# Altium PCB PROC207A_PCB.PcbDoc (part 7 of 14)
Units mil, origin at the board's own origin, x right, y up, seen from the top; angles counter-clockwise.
Board outline 4094.49 x 3724.79 mil, 8 copper layers (Top Layer, L2_GND1, L3_SIG1, L4_PWR1, L5_PWR2, L6_SIG2, L7_GND2, Bottom Layer), stack 58.1 mil thick; 584 components, 399 nets, 8440 pads, 5258 vias.
Unrouted connection lines stored in the file: 9.
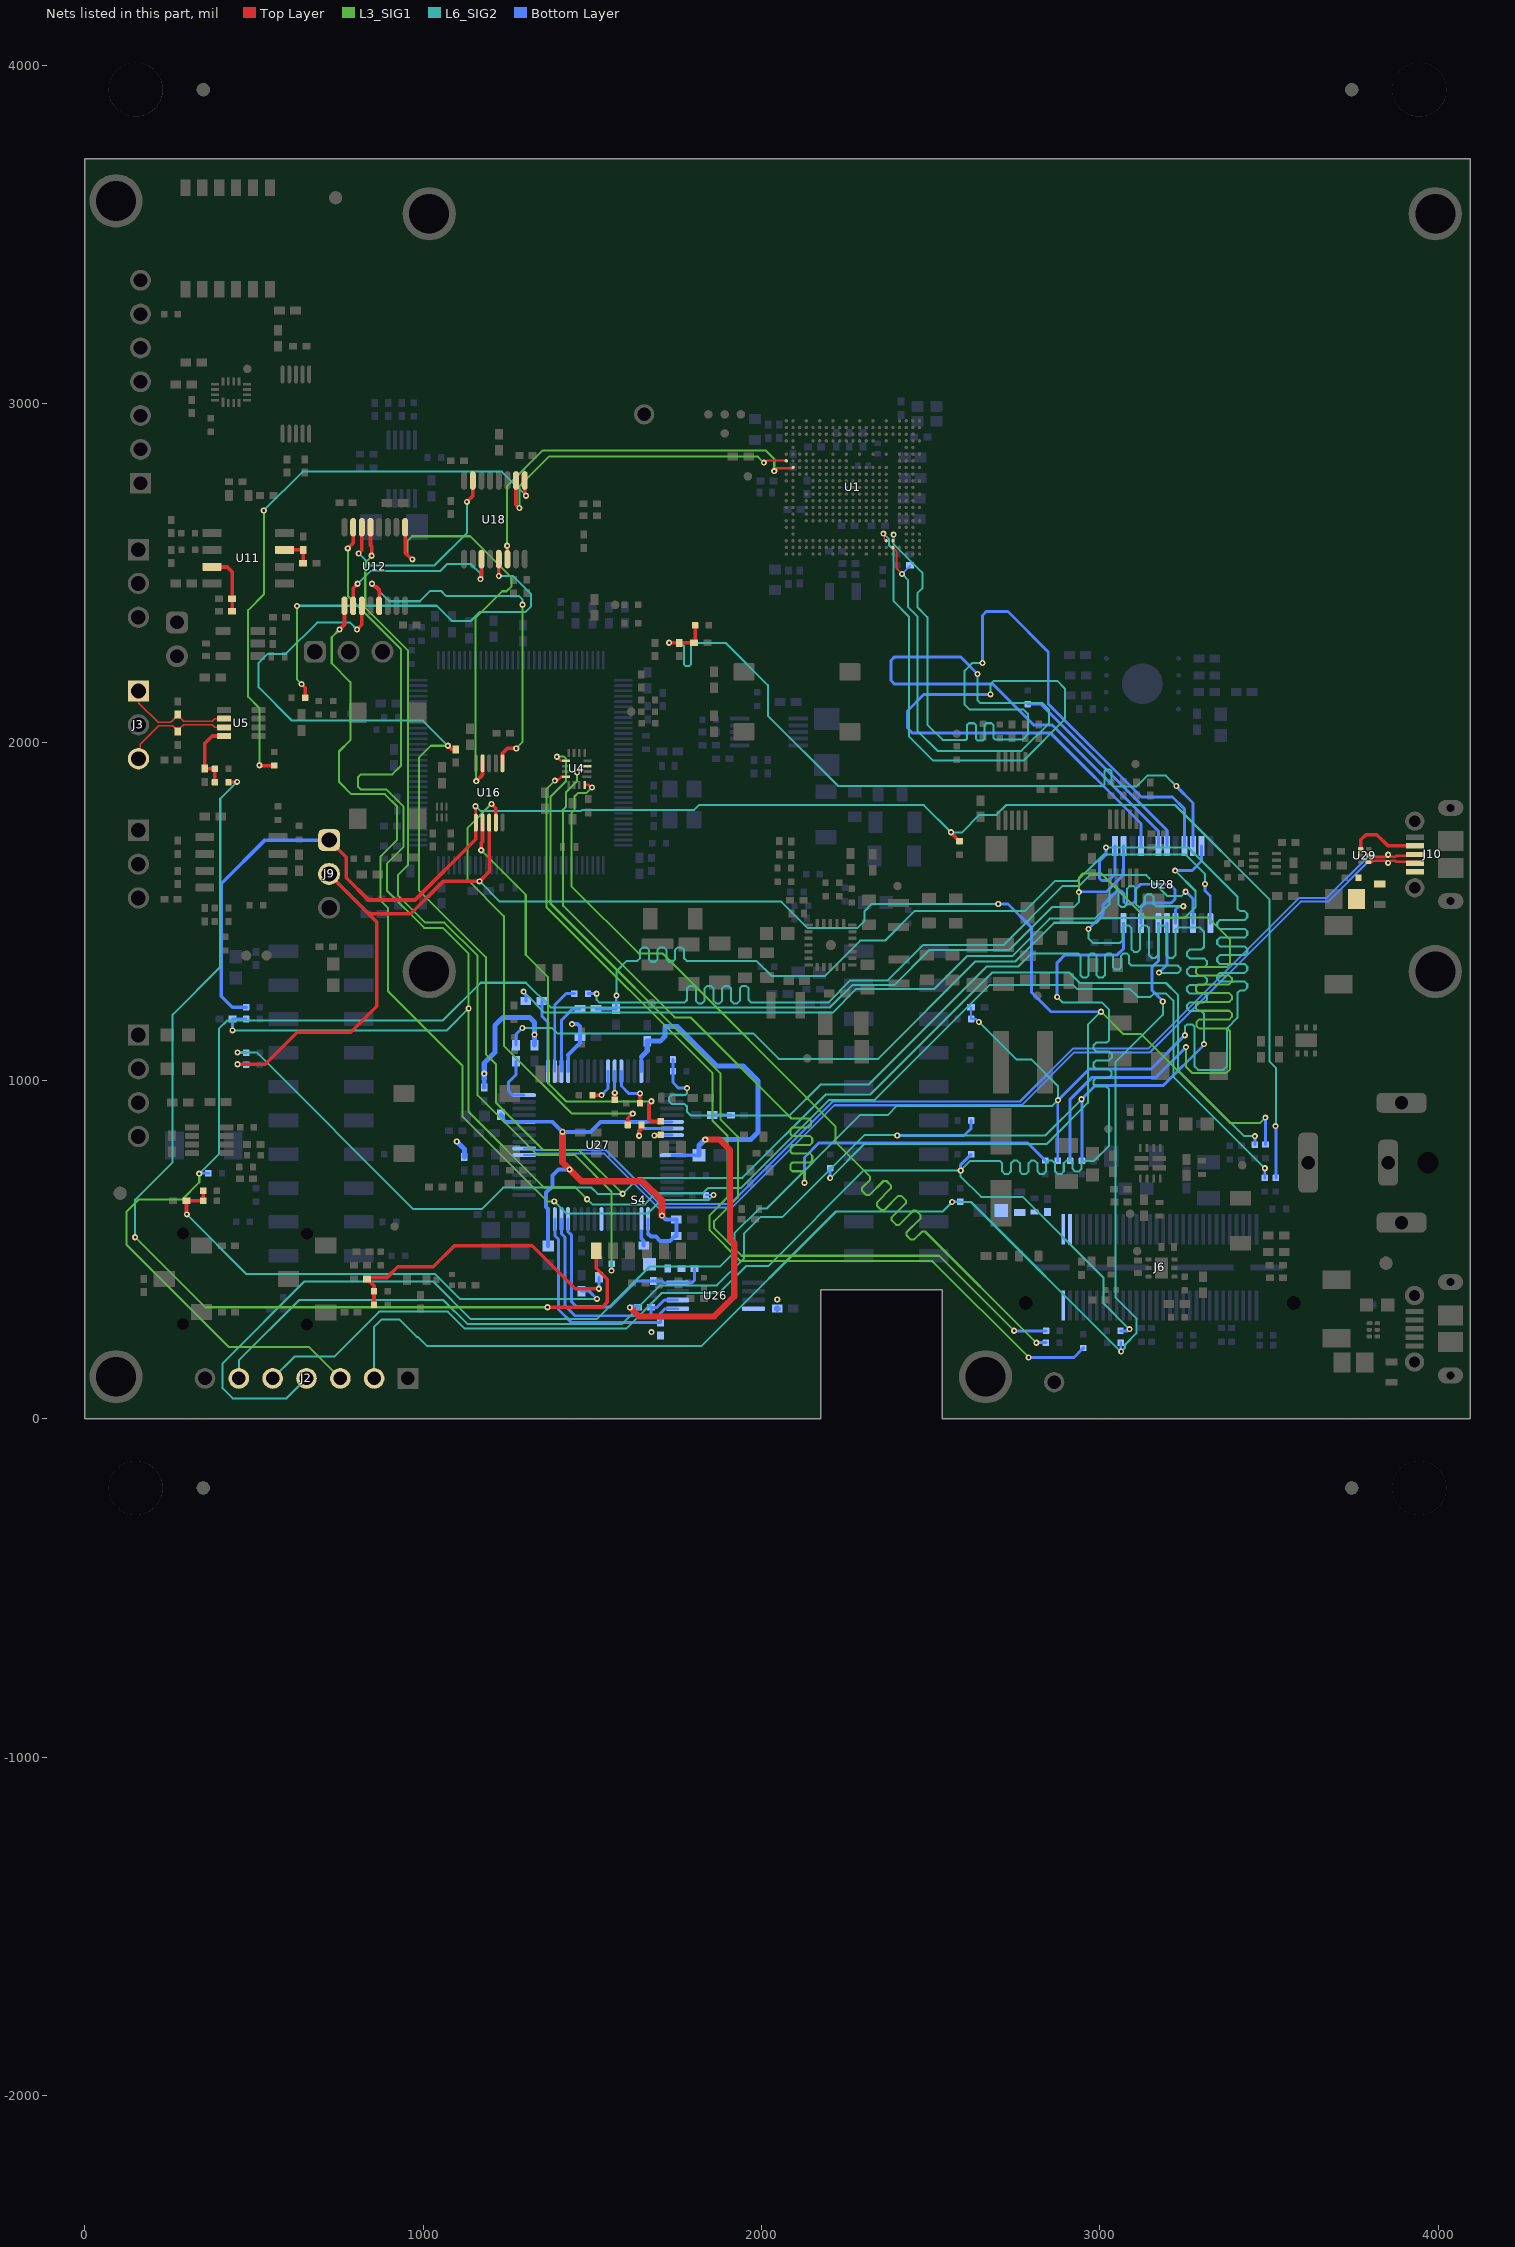
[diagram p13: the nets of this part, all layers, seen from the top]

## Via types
v1: diameter 13.77, hole 7, Top Layer to L2_GND1, tented top, 4306 vias
v2: diameter 18, hole 8, Top Layer to Bottom Layer, tented both sides, 946 vias
v3: diameter 19.68, hole 8, Top Layer to Bottom Layer, tented both sides, 6 vias

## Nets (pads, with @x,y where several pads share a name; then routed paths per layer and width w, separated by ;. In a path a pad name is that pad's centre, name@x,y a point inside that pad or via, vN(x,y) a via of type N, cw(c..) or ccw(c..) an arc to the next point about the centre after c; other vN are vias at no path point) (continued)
CAN_FD_H: J3.3 R68.2 U5.7 | length 335.9
  Top Layer w4.3: J3.3@158.23,1951.41 163.25,1956.42 163.25,1994.38 218.41,2049.54 258.93,2049.54 266.49,2041.98 266.49,2041.51 273.71,2034.29 274.18,2034.29 R68.2@274.18,2031.85 ; R68.2@274.18,2034.64 275,2034.64 281.87,2041.51 281.87,2042.33 291.5,2051.95 376.56,2051.95 384.46,2044.06 U5.7@411.27,2044.06
CAN_FD_L: J3.1 R79.1 U5.6 | length 332.4
  Top Layer w4.3: J3.1@158.23,2151.41 159.7,2149.95 159.7,2115.98 216.34,2059.34 253.84,2059.34 266.49,2071.99 266.49,2072.19 R79.1@274.18,2079.88 ; R79.1@274.18,2081.85 R79.1@274.18,2079.88 ; U5.6@411.27,2069.65 384.46,2069.65 376.56,2061.75 292.32,2061.75 281.88,2072.19 R79.1@274.18,2079.88
CAN_FD_RX: R80.1 U18.5 | length 1212
  Top Layer w10.8: v2(640.3,2171.85) 651.32,2160.83 R80.1@651.32,2132.1 ; U18.5@1223.27,2541.56 1223.38,2541.44 1223.38,2491.76 v2(1223.5,2491.65)
  L3_SIG1 w6: v2(627.14,2402.65) 627.14,2185.02 v2(640.3,2171.85)
  L6_SIG2 w6: v2(627.14,2402.65) 628.06,2403.58 1039.61,2403.58 1084.25,2358.93 1141.19,2358.93 1167.77,2385.51 1302.58,2385.51 1318.08,2401.02 1318.08,2438.63 1265.06,2491.65 v2(1223.5,2491.65)
CAN_FD_TX: R78.1 U18.9 | length 1730.1
  Top Layer w10.8: v2(515.55,1931.96) 516.43,1931.08 R78.1@559.82,1931.08 ; U18.9@1300.04,2773.84 1300.04,2734.71 1304.03,2730.71 v2(1304.03,2728.77)
  L3_SIG1 w6: v2(515.55,1931.96) 515.55,2101.32 482.32,2134.55 482.32,2390.56 528.65,2436.9 v2(528.65,2685.28)
  L6_SIG2 w6: v2(528.65,2685.28) 643.45,2800.07 1232.73,2800.07 v2(1304.03,2728.77)
CAN_FD_UARTA_RX: U1.Y8 U18.6 | length 1155.5
  Top Layer w8: v2(2037.65,2801.29) 2046.44,2810.09 2090.45,2810.09 2092.66,2812.3 U1.Y8@2093.15,2812.3
  Top Layer w10.8: v2(1248.01,2581) 1248.43,2580.57 1248.43,2541.98 U18.6@1248.86,2541.56
  L3_SIG1 w6: v2(1248.01,2581) 1248.01,2757.64 1352.17,2861.81 2013.17,2861.81 2025,2849.98 2037.65,2837.33 v2(2037.65,2801.29)
CAN_FD_UARTA_TX: U1.AA7 U18.10 | length 985.5
  Top Layer w6: v2(2006.99,2826.66) 2010.24,2826.66 2016.23,2832.65 2072.81,2832.65 U1.AA7@2073.47,2831.99
  Top Layer w10.8: U18.10@1274.45,2773.84 1274.45,2701.85 v2@1283.85,2692.44
  L3_SIG1 w6: v2(1284.02,2692.61) 1284.02,2757.06 1371.46,2844.49 1989.16,2844.49 v2(2006.99,2826.66)
CAN_STB: R3.2 R71.2 R273.2 U5.8 | length 210.6
  Top Layer w10.8: R3.2@384.18,1881.85 R273.2@384.18,1921.85 R71.2@354.18,1921.85 354.18,1996.18 376.47,2018.47 U5.8@411.27,2018.47
CAN_STB_CTRL: R3.1 S4.1 | length 3150.3
  Top Layer w10.8: R3.1@424.54,1881.85 448.85,1881.85 v2(450,1883) ; v2(1367.57,329.83) 1528.82,329.83 1544.1,345.11 1544.1,412.9 1511.51,445.49 S4.1@1511.51,496.87
  L3_SIG1 w6: v2(148.34,536.68) 355.19,329.83 v2(1367.57,329.83)
  L6_SIG2 w6: v2(148.34,536.68) 148.34,647.84 259.37,758.88 259.37,1195.03 400,1335.65 400,1833 v2(450,1883)
CONN_5V: C92.1 C93.1 C96.2 J6.1 J6.2 J6.3 R30.2
DCA_LP_FTDI_HOST_INTR_1: R81.2 R261.2 R276.1 U28.10 | length 2289.3
  Top Layer w10.8: v2(1726.91,2294.09) R261.2@1757.13,2294.09 1757.38,2294.33 R276.1@1800.3,2294.33 1803.93,2297.96 R81.2@1803.93,2345.54
  L6_SIG2 w6: v2(1726.91,2294.09) 1762.33,2294.09 1770.52,2285.89 1770.52,2230.07 1775.62,2224.97 1785.82,2224.97 1790.92,2230.07 1790.92,2288.99 1796.02,2294.09 1893.54,2294.09 2019,2168.63 2019,2078 2226,1871 3010.63,1871 3014.49,1874.86 3014.49,1914.66 3019.59,1919.76 3029.79,1919.76 3034.89,1914.66 3034.89,1874.86 3039.99,1869.76 3108.73,1869.76 3140.49,1901.52 3195.22,1901.52 v2(3226.13,1870.61)
  Bottom Layer w8.7: v2(3226.13,1870.61) 3226.13,1870.1 3275.37,1820.87 U28.10@3275.37,1693.39
DCA_LP_FTDI_SPIA_CLK: U1.F19 U28.4 | length 2741
  Top Layer w4: v2(2360.3,2616.69) 2362.57,2614.43 2362.57,2601.94 U1.F19@2368.75,2595.77
  L6_SIG2 w6: v2(2360.3,2616.69) 2377.31,2599.68 2377.31,2581.54 2389.55,2569.3 2389.55,2418 2435.85,2371.69 2435.85,2018.2 2508.08,1945.97 2774.35,1945.97 2897.78,2069.4 2897.78,2157.5 2874.03,2181.25 2686.1,2181.25 2676.86,2172.01 v2(2676.86,2141.67)
  Bottom Layer w8.7: v2(2676.86,2141.67) 2480.34,2141.67 2431.19,2092.51 2431.19,2041.87 2446.22,2026.83 2855.21,2026.83 3121.82,1760.22 U28.4@3121.82,1693.39
DCA_LP_FTDI_SPIA_CS: R246.1 U1.E20 U28.6 | length 2757.4
  Top Layer w4: U1.E20@2388.43,2576.08 2399.35,2565.16 2399.35,2550.22
  Top Layer w6: 2399.12,2550.22 2399.12,2513.98 v2(2415.49,2497.61)
  L6_SIG2 w6: v2(2415.49,2497.61) 2433.72,2479.38 2433.72,2399.49 2460.77,2372.44 2460.77,2033.68 2520.13,1974.32 2768.34,1974.32 2850.43,2056.41 2850.43,2096.44 2831.01,2115.86 2646.6,2115.86 2638.61,2123.85 v2(2638.61,2202.01)
  Bottom Layer w4: v2(2415.49,2497.61) 2439.12,2521.24 R246.1@2439.12,2523.33
  Bottom Layer w8.7: v2(2638.61,2202.01) 2588,2252.62 2393.57,2252.62 2382.42,2241.47 2382.42,2182.27 2392.9,2171.79 2683.94,2171.79 2804.27,2051.45 2858.85,2051.45 3173,1737.3 U28.6@3173,1693.39
DCA_LP_FTDI_SPIA_MISO: R284.1 U28.7 | length 612.5
  Bottom Layer w8.7: R284.1@2787,2112.82 2825.59,2112.82 3198.59,1739.82 U28.7@3198.59,1693.39
DCA_LP_FTDI_SPIA_MOSI: U1.E19 U28.9 | length 2738
  Top Layer w4: U1.E19@2388.43,2595.77 2388.94,2596.27 2388.94,2611.99 v2(2390.69,2613.75)
  L6_SIG2 w6: v2(2390.69,2613.75) 2390.69,2585.9 2475.34,2501.25 2475.34,2455.09 2460.63,2440.38 2460.63,2399.86 2490.34,2370.15 2490.34,2051.94 2535.22,2007.06 2604.5,2007.06 2607.46,2010.03 2607.46,2050.99 2612.66,2056.19 2628.26,2056.19 2633.46,2050.99 2633.46,2010.03 2638.66,2004.83 2654.26,2004.83 2659.46,2010.03 2659.46,2050.99 2664.66,2056.19 2680.26,2056.19 2685.46,2050.99 2685.46,2013.01 2690.66,2007.81 2771.73,2007.81 2787.18,2023.26 2787.18,2084.46 2775.15,2096.49 2615.41,2096.49 2600.46,2111.43 2600.46,2211.94 2622.93,2234.4 v2(2653.01,2234.4)
  Bottom Layer w8.7: v2(2653.01,2234.4) 2653.01,2375.07 2664.2,2386.26 2728.35,2386.26 2847.67,2266.93 2847.67,2113.37 3123.16,1837.88 3215.13,1837.88 3249.77,1803.24 U28.9@3249.77,1693.39
DCA_LP_FTDI_UARTA_RX: U12.5 U16.6 | length 1090
  Top Layer w10.8: v2(848.58,2468.46) 857.66,2459.37 862.05,2459.37 869.69,2451.74 U12.5@869.69,2403.24 ; U16.6@1234.33,1937.85 1234.33,1967.62 1248.53,1981.82 v2(1274.86,1981.82)
  L3_SIG1 w6: v2(1274.86,1981.82) 1293.22,2000.18 v2(1293.22,2406.58)
  L6_SIG2 w6: v2(848.58,2468.46) 900.17,2416.87 989.72,2416.87 1020.36,2447.51 1052.49,2447.51 1067.01,2432.99 1282.65,2432.99 1293.22,2422.42 v2(1293.22,2406.58)
DCA_LP_FTDI_UARTA_TX: U12.9 U16.9 | length 1244.2
  Top Layer w10.8: U12.9@946.46,2635.52 946.46,2560.05 965.88,2540.63 v2(967.81,2540.63) ; v2(1156.63,1884.99) 1156.79,1884.99 1175.28,1903.47 U16.9@1175.28,1937.85
  L3_SIG1 w6: v2(967.81,2540.63) 954.15,2554.28 954.15,2595.9 967.26,2609 1138.74,2609 1261.53,2486.21 1261.53,2461.8 1246.18,2446.45 1233.64,2446.45 1154.18,2366.99 1154.18,1960.86 1156.63,1958.42 v2(1156.63,1884.99)
DCA_LP_HOST_INTR_1: J2.2 R42.2 R223.2 U28.19 | length 4198.8
  L6_SIG2 w6: J2.2@854.92,119.45 854.92,272.12 876.8,294 928.56,294 980.41,242.15 984,242.15 1010.65,215.5 1822.94,215.5 2220.24,612.8 2535.38,612.8 v2(2563.66,641.08) 2619.37,641.08 3061.52,198.93 v2(3063.04,198.93) 3075.08,210.97 3075.08,219.79 3108.12,252.83 3108.12,297.29 3046.05,359.37 3046.05,1054.09 3186.19,1194.23 v2(3186.19,1233.93)
  Bottom Layer w8.7: v2(2563.66,641.08) 2564.22,641.64 R223.2@2587.42,641.64 ; v2@3061.92,202.02 R42.2@3061.92,225.06 ; U28.19@3173,1465.05 3173,1353.12 3153.78,1333.9 3153.78,1267.82 3186.19,1235.41 v2(3186.19,1233.93)
DCA_LP_RS232_RX: R61.1 R163.1 R178.1 U12.3 | length 6741.8
  Top Layer w10.8: v2(804.3,2333.27) 818.51,2347.48 U12.3@818.51,2403.24 ; v2(1072.67,1989.7) 1083.03,1979.33 R163.1@1096.46,1979.33
  L3_SIG1 w6: v2(1072.67,1989.7) 1022.63,1989.7 987.23,1954.3 987.23,1562.77 1185,1365 1185,1078.11 1215.73,1047.38 1215.73,933.58 1354.56,794.75 1460.07,794.75 v2(1589.52,665.3)
  L6_SIG2 w6: v2(450.77,1083.11) 507.44,1083.11 970.7,619.86 1173.07,619.86 1236.5,683.29 1497.43,683.29 1515.42,665.3 v2(1589.52,665.3) 1636.46,712.23 1943.23,712.23 2189.85,958.85 2321.16,958.85 2681.8,1319.49 2910.02,1319.49 2941.06,1288.45 3195.67,1288.45 3230.97,1253.14 3230.97,1032.03 3427.27,835.73 v2(3458.23,835.73) ; v2(804.3,2333.27) 783.74,2353.83 686.61,2353.83 593.87,2261.09 539.9,2261.09 513.58,2234.77 513.58,2162.14 612.04,2063.68 998.68,2063.68 v2(1072.67,1989.7)
  Bottom Layer w8.7: v2(450.77,1083.11) 451.32,1082.56 476.13,1082.56 R178.1@476.69,1082 ; v2(3458.23,835.73) 3458.35,835.61 R61.1@3458.35,810.38
DCA_LP_RS232_TX: R62.1 R156.1 R176.1 U12.15 | length 6088
  Top Layer w10.8: v2(776.95,2573.24) 792.92,2589.21 U12.15@792.92,2635.52
  L3_SIG1 w6: v2(776.95,2573.24) 776.95,2432.3 934.91,2274.33 934.91,1931.27 908.67,1905.03 815.91,1905.03 806.65,1895.77 806.65,1869.25 814.97,1860.93 891.06,1860.93 941.55,1810.44 941.55,1690.04 892.74,1641.23 892.74,1561.86 1002.98,1451.63 1057.41,1451.63 1134.26,1374.77 v2(1134.26,1213.18) 1134.26,906.98 1356.81,684.43 1449.29,684.43 v2(1484.69,649.03)
  L6_SIG2 w6: v2(436.29,1148.35) 436.57,1148.07 1069.15,1148.07 v2(1134.26,1213.18) ; v2(1484.69,649.03) 1499.72,634 1655.11,634 1687.97,666.86 1826.35,666.86 1841.49,682 1938.67,682 2199.67,943 2335.08,943 2674.97,1282.9 2920.59,1282.9 2933.32,1270.16 3090.13,1270.16 3113.41,1246.88 3149.46,1246.88 3159.76,1257.17 3196.04,1257.17 3217.26,1235.96 3217.26,1011.15 v2(3487.76,740.65)
  Bottom Layer w8.7: v2(436.29,1148.35) 436.49,1148.55 436.49,1181.8 R156.1@436.69,1182 R176.1@476.69,1182 ; R62.1@3487.69,712.42 v2(3487.76,740.65) v2(3487.76,740.65)
DCA_LP_SPIA_CLK: J2.3 R41.1 R210.1 U28.2 | length 7185.7
  L3_SIG1 w6: v2(337.89,724.65) 337.89,698.83 287.45,648.4 158.52,648.4 123.12,613 123.12,513.88 424.36,212.64 661.73,212.64 J2.3@754.92,119.45 ; v2(2938.09,1556.86) 2938.09,1599.99 2950.1,1612 3004.71,1612 3135.08,1481.62 3320.9,1481.62 3384.44,1418.08 3384.44,1373.1 3384.44,1344.1 3376.64,1336.3 3291.88,1336.3 3284.08,1328.5 3284.08,1318.1 3291.88,1310.3 3382.41,1310.3 3390.21,1302.5 3390.21,1292.1 3382.41,1284.3 3291.88,1284.3 3284.08,1276.5 3284.08,1266.1 3291.88,1258.3 3382.41,1258.3 3390.21,1250.5 3390.21,1240.1 3382.41,1232.3 3291.88,1232.3 3284.08,1224.5 3284.08,1214.1 3291.88,1206.3 3382.41,1206.3 3390.21,1198.5 3390.21,1188.1 3382.41,1180.3 3293.12,1180.3 3285.32,1172.5 3285.32,1162.1 3293.12,1154.3 3376.64,1154.3 3384.44,1146.5 3384.44,1107.61 3384.44,1032.54 3374.22,1022.32 3272.83,1022.32 3254.89,1040.27 v2(3254.89,1098.65)
  L6_SIG2 w6: v2(337.89,724.65) 395.98,782.75 395.98,1152.6 421.3,1177.91 1058.45,1177.91 1169.61,1289.07 1303.52,1289.07 1376.39,1216.2 2202.56,1216.2 2268.64,1282.28 2392.36,1282.28 2495.92,1385.84 2732.08,1385.84 2858.74,1512.5 2923.3,1512.5 2938.09,1527.28 v2(2938.09,1556.86)
  Bottom Layer w8.7: v2(337.89,724.65) 339.24,726 R210.1@364.65,726 ; R41.1@2912.47,762.75 2912.47,944.88 2976.03,1008.44 3164.67,1008.44 v2(3254.89,1098.65) ; v2(2938.09,1556.86) 2939.37,1558.14 3019.84,1558.14 3070.64,1608.93 U28.2@3070.64,1693.39
DCA_LP_SPIA_CS: J2.4 R39.1 R173.1 R177.2 U28.1 | length 6484.4
  L6_SIG2 w6: J2.4@654.92,119.45 595.93,60.46 436.54,60.46 406.99,90.01 406.99,164.2 648.74,405.95 1029.51,405.95 1140.96,294.51 1513.35,294.51 1668.84,450 1876.64,450 1919.49,492.85 1919.49,548.06 1993.06,621.64 2014.83,621.64 2291.99,898.8 2374.29,898.8 2400.38,924.89 2859.49,924.89 v2(2876.51,941.92) 2876.51,983.72 2797.73,1062.5 2753.33,1062.5 v2(2642.48,1173.35) ; v2(3018.05,1688.88) 3262.04,1688.88 3406.91,1544.01 3406.91,1511.41 3406.91,1508.41 3414.71,1500.61 3428.12,1500.61 3435.92,1492.81 3435.92,1482.41 3428.12,1474.61 3354.99,1474.61 3347.19,1466.81 3347.19,1456.41 3354.99,1448.61 3428.12,1448.61 3435.92,1440.81 3435.92,1430.41 3428.12,1422.61 3354.99,1422.61 3347.19,1414.81 3347.19,1404.41 3354.99,1396.61 3428.12,1396.61 3435.92,1388.81 3435.92,1378.41 3428.12,1370.61 3354.99,1370.61 3347.19,1362.81 3347.19,1352.41 3354.99,1344.61 3428.12,1344.61 3435.92,1336.81 3435.92,1326.41 3428.12,1318.61 3354.99,1318.61 3347.19,1310.81 3347.19,1300.41 3354.99,1292.61 3428.12,1292.61 3435.92,1284.81 3435.92,1274.41 3428.12,1266.61 3414.71,1266.61 3406.91,1258.81 3406.91,1231.05 3406.91,1185.07 3376.37,1154.52 3376.37,1042.29 3365.46,1031.38 3290.98,1031.38 3279.93,1042.43 3279.93,1159.25 3272.95,1166.23 3258.14,1166.23 3251.92,1160 3251.92,1134.32 v2(3251.43,1133.83)
  Bottom Layer w6: R177.2@2619.84,1182 2633.83,1182 v2(2642.48,1173.35) ; R177.2@2619.84,1182 R173.1@2619.86,1216.29
  Bottom Layer w8.7: R39.1@2875.7,762.75 v2@2875.7,941.92 ; v2(2876.51,941.92) 2969.05,1034.45 3152.05,1034.45 v2(3251.43,1133.83) ; v2(3018.05,1688.88) 3018.05,1666.45 2999.29,1647.69 2999.29,1597.68 3005.91,1591.06 3026.28,1591.06 3045.05,1609.83 U28.1@3045.05,1693.39
DCA_LP_SPIA_MISO: J2.5 R53.2 R221.2 U28.23 | length 5137.9
  L6_SIG2 w6: J2.5@554.92,119.45 619.47,184 737,184 870,317 1072.86,317 1122.94,266.92 1600.32,266.92 1705.88,372.48 1875.23,372.48 1954.08,451.33 2019.35,451.33 2302.41,734.39 v2(2588.84,734.39) ; v2(2873.93,1246.88) 2889.76,1231.05 3005.63,1231.05 3027.5,1209.18 3027.5,1119.6 3019.7,1111.8 2989.17,1111.8 2981.37,1104 2981.37,1093.6 2989.17,1085.8 3027.69,1085.8 3035.49,1078 3035.49,1067.6 3027.69,1059.8 2989.17,1059.8 2981.37,1052 2981.37,1041.6 2989.17,1033.8 3026.25,1033.8 3034.05,1026 3034.05,1015.6 3026.25,1007.8 2989.17,1007.8 2981.37,1000 2981.37,989.6 2989.17,981.8 3019.7,981.8 3027.5,974 3027.5,807.1 2982.92,762.52 2953.26,762.52 2945.46,754.72 2945.46,738.61 2937.66,730.81 2927.26,730.81 2919.46,738.61 2919.46,755.68 2911.66,763.48 2901.26,763.48 2893.46,755.68 2893.46,731.41 2885.66,723.61 2875.26,723.61 2867.46,731.41 2867.46,755.68 2859.66,763.48 2849.26,763.48 2841.46,755.68 2841.46,731.41 2833.66,723.61 2823.26,723.61 2815.46,731.41 2815.46,755.68 2807.66,763.48 2797.26,763.48 2789.46,755.68 2789.46,731.41 2781.66,723.61 2771.26,723.61 2763.46,731.41 2763.46,755.68 2755.66,763.48 2745.26,763.48 2737.46,755.68 2737.46,731.41 2729.66,723.61 2719.26,723.61 2711.46,731.41 2711.46,754.72 2703.66,762.52 2616.97,762.52 v2(2588.84,734.39) ; v2(3087.5,265.08) 3010.91,341.68 3010.91,416.76 2771.68,655.99 2648.98,655.99 2588.84,716.13 v2(2588.84,734.39)
  Bottom Layer w8.7: v2@2588.84,735.37 2588.84,750.99 R221.2@2619.84,782 ; v2(2873.93,1246.88) 2873.93,1348.36 2897.16,1371.58 3051.63,1371.58 3070.64,1390.59 U28.23@3070.64,1465.05 ; R53.2@3061.32,260.03 3082.45,260.03 v2(3087.5,265.08)
DCA_LP_SPIA_MOSI: J2.6 R52.1 R201.2 U28.21 | length 6033.3
  L6_SIG2 w6: J2.6@454.92,119.45 454.92,173.23 632.69,351 1060,351 1131.2,279.8 1586.7,279.8 1701.23,394.33 1868.24,394.33 1948.74,474.83 1948.74,548 1997.91,597.17 2062.49,597.17 2304.08,838.77 2395.68,838.77 2398.38,836.07 2398.38,834.63 v2(2401.22,837.47) 2839.06,837.47 v2(2946.19,944.6) ; v2(2966.41,1447.95) 2966.41,1420.12 2979.58,1406.95 3030.78,1406.95 3059.73,1406.95 3067.53,1414.75 3067.53,1450.92 3075.33,1458.72 3085.73,1458.72 3093.53,1450.92 3093.53,1388.4 3101.33,1380.6 3111.73,1380.6 3119.53,1388.4 3119.53,1450.92 3127.33,1458.72 3137.73,1458.72 3145.53,1450.92 3145.53,1370.1 3153.33,1362.3 3163.73,1362.3 3171.53,1370.1 3171.53,1450.92 3179.33,1458.72 3189.73,1458.72 3197.53,1450.92 3197.53,1370.1 3205.33,1362.3 3215.73,1362.3 3223.53,1370.1 3223.53,1444.15 3231.33,1451.95 3234.33,1451.95 3296.13,1451.95 3308,1440.08 3308,1423.85 3308,1394.85 3300.2,1387.05 3265.62,1387.05 3257.82,1379.25 3257.82,1368.85 3265.62,1361.05 3308.5,1361.05 3316.3,1353.25 3316.3,1342.85 3308.5,1335.05 3265.62,1335.05 3257.82,1327.25 3257.82,1316.85 3265.62,1309.05 3308.5,1309.05 3316.3,1301.25 3316.3,1290.85 3308.5,1283.05 3265.62,1283.05 3257.82,1275.25 3257.82,1264.85 3265.62,1257.05 3308.5,1257.05 3316.3,1249.25 3316.3,1238.85 3308.5,1231.05 3266.22,1231.05 3258.42,1223.25 3258.42,1212.85 3266.22,1205.05 3300.2,1205.05 3308,1197.25 3308,1123.7 v2(3308,1107.61)
  Bottom Layer w8.7: v2(2401.22,837.47) 2598.95,837.47 2619.84,858.36 R201.2@2619.84,882 ; R52.1@2947.46,763.19 2946.83,763.83 2946.83,943.96 v2(2946.19,944.6) 2986.77,985.18 3187.84,985.18 3308,1105.34 v2(3308,1107.61) ; v2(2966.41,1447.95) 3008.88,1490.43 3008.88,1518.44 3050.29,1559.84 3064.09,1559.84 3071.14,1552.79 3071.14,1528.06 3077.16,1522.03 3095.87,1522.03 3105.7,1531.86 3105.7,1565.15 3120.9,1580.35 3206.4,1580.35 3222.55,1564.2 3222.55,1536.08 3211.13,1524.66 3131.47,1524.66 3121.82,1515.01 U28.21@3121.82,1465.05
DCA_LP_UARTA_RX: J9.2 R152.2 R198.1 R212.1 U16.3 | length 5574.7
  Top Layer w10.8: v2(450.77,1048.11) 533.23,1048.11 627.75,1142.63 785.87,1142.63 862.56,1219.32 862.56,1468.75 838.3,1493 ; J9.2@721.75,1610.85 721.75,1609.55 838.3,1493 ; U16.3@1194.96,1762.65 1194.96,1617.11 v2(1166.6,1588.75) 1058.75,1588.75 963,1493 838.3,1493
  L3_SIG1 w6: v2(3003.26,1203.32) 3003.77,1203.32 3070.09,1137 3122,1137 3384.32,874.68 3473.82,874.68 v2(3489.49,890.35)
  L6_SIG2 w6: v2(1166.6,1588.75) 1226.35,1529 2058.78,1529 2137.24,1450.53 2283.42,1450.53 2304.83,1471.94 2304.83,1501.11 2325.9,1522.18 v2(2699.72,1522.18) ; v2(2203,711.78) 2303.72,812.5 2843.41,812.5 2964.75,933.84 2964.75,1164.82 v2(3003.26,1203.32)
  Bottom Layer w8.7: v2(450.77,1048.11) 451.32,1047.56 476.13,1047.56 R198.1@476.69,1047 ; R212.1@2202.92,741.15 R212.1@2202.92,741.15 2202.96,711.83 v2(2203,711.78) ; v2(2699.72,1522.18) 2728.95,1522.18 2797.67,1453.47 2797.67,1261.73 2856.07,1203.32 v2(3003.26,1203.32) ; v2(3489.49,890.35) 3489.84,890 R152.2@3489.84,810.87
DCA_LP_UARTA_TX: J9.1 R153.2 R180.1 R182.1 U16.1 | length 4918
  Top Layer w7: v2(1154.8,1810.99) 1155.59,1810.19 U16.1@1155.59,1762.65
  Top Layer w10.8: J9.1@721.75,1710.85 772.15,1660.44 772.15,1599.85 838.18,1533.82 975.96,1533.82 1155.59,1713.45 U16.1@1155.59,1762.65 ; v2(2560.1,1733.94) 2560.1,1732.95 2580.98,1712.07 2580.98,1711.58 2584.93,1707.63 R182.1@2585.42,1707.63
  L6_SIG2 w6: v2(1154.8,1810.99) 1169.54,1796.25 1466.17,1796.25 1469.52,1799.6 1800.06,1799.6 1814.54,1814.08 2479.96,1814.08 v2(2560.1,1733.94) 2592.94,1733.94 2644.26,1785.26 2694.45,1785.26 2723.77,1814.57 3222.3,1814.57 3501.09,1535.79 3501.09,1057.11 3520.61,1037.59 3520.61,866.56 v2(3519.21,865.16)
  Bottom Layer w8.7: v2(3519.21,865.16) 3520.34,864.03 R153.2@3520.34,712.42
  Bottom Layer w10.8: R180.1@476.69,1217 435.33,1217 403.24,1249.1 403.24,1582.09 531.99,1710.85 J9.1@721.75,1710.85
DCA_TCK: R38.2 U4.16 | length 2807.7
  Top Layer w7: U4.16@1477.36,1874.02 1488.92,1874.02 1496.73,1866.21 v2(1498.62,1866.21)
  L3_SIG1 w6: v2(1498.62,1866.21) 1482.1,1849.69 1457.27,1849.69 1447.22,1839.64 1447.22,1799.4 1438.17,1790.35 1438.17,1574.83 1637,1376 1707.31,1376 2219.35,863.96 2219.35,817.84 2321.13,716.06 2321.13,707.3 2297.16,683.33 2297.16,674.56 2310.32,661.41 2319.09,661.41 2360.73,703.05 2369.5,703.05 2382.65,689.9 2382.65,681.13 2340.86,639.35 2340.86,630.58 2354.02,617.43 2362.78,617.43 2404.57,659.21 2413.34,659.21 2426.49,646.06 2426.49,637.29 2384.7,595.51 2384.7,586.74 2397.86,573.59 2406.62,573.59 2448.41,615.37 2457.18,615.37 2470.33,602.22 2470.33,593.45 2428.55,551.67 2428.55,542.9 2441.7,529.75 2450.47,529.75 2474.57,553.85 2483.34,553.85 v2(2812.38,224.81)
  Bottom Layer w8.7: v2(2812.38,224.81) 2812.63,225.06 R38.2@2840.7,225.06
DCA_TDI: R37.1 U4.3 | length 2773.9
  Top Layer w7: v2(1454.98,1910.64) 1454.98,1913.18 1470.93,1929.13 U4.3@1485.24,1929.13
  L3_SIG1 w6: v2(1454.98,1910.64) 1454.98,1885.58 1421.98,1852.58 1421.98,1809.06 1413.39,1800.47 1413.39,1516.61 1743.49,1186.51 1790.12,1186.51 2076.64,900 2088.77,887.87 2140.12,887.87 2146.62,881.37 2146.62,868.37 2140.12,861.87 2091.51,861.87 2085.01,855.37 2085.01,842.37 2091.51,835.87 2143.5,835.87 2150,829.37 2150,816.37 2143.5,809.87 2091.51,809.87 2085.01,803.37 2085.01,790.37 2091.51,783.87 2143.5,783.87 2150,777.37 2150,764.37 2143.5,757.87 2091.51,757.87 2085.01,751.37 2085.01,738.37 2091.51,731.87 2120.5,731.87 2127,725.37 2127,722.37 v2(2127,698)
  Bottom Layer w8.7: v2(2127,698) 2127,772.58 2170.24,815.82 2786.31,815.82 R37.1@2838.5,763.64
DCA_TDO: R34.2 U4.9 | length 2834.6
  Top Layer w7: v2(1394.94,1957.23) 1407.29,1944.88 U4.9@1422.24,1944.88
  L3_SIG1 w6: v2(1394.94,1957.23) 1416.62,1957.23 1422.01,1951.84 1422.01,1884.37 1376.33,1838.69 1376.33,1523.39 1878.37,1021.36 1878.37,886.22 1930.14,834.44 1930.14,654.94 1859.74,584.54 1859.74,563.85 1941.47,482.12 2525.13,482.12 v2(2746.75,260.5)
  Bottom Layer w8.7: v2(2746.75,260.5) 2747.22,260.03 R34.2@2841.3,260.03
DCA_TMS: R40.2 U4.12 | length 2893.8
  Top Layer w7: v2(1389.15,1886.55) 1391.25,1888.65 1398.95,1888.65 1407.93,1897.64 U4.12@1422.24,1897.64
  L3_SIG1 w6: v2(1389.15,1886.55) 1364.11,1861.51 1364.11,1512.94 1855.66,1021.39 1855.66,880.41 1899.5,836.57 1899.5,654.55 1845.63,600.68 1845.63,558.6 1937.95,466.28 2504.99,466.28 v2(2789.7,181.57)
  Bottom Layer w8.7: v2(2789.7,181.57) 2923.38,181.57 2945.82,204 2945.82,204.5 2950.82,209.5 R40.2@2951.31,209.5
EECLK: R167.1 U26.2 U27.62 | length 634.8
  Bottom Layer w8.7: U27.62@1408.58,590.55 1408.58,547.03 1419.14,536.47 1419.14,334.19 1448.63,304.7 1665.59,304.7 1673.82,312.94 R167.1@1673.82,329.65 ; R167.1@1673.82,329.65 1691.33,329.62 1712.8,351.09 U26.2@1751.97,351.09
EECS: R168.1 U26.1 U27.63 | length 672.8
  Bottom Layer w8.7: U27.63@1388.9,590.55 1388.9,541.81 1399.94,530.77 1399.94,323.35 1438.92,284.36 1700.4,284.36 R168.1@1701.29,285.25 1701.29,312.22 1714.57,325.5 U26.1@1751.97,325.5
EEDATA: R184.1 R185.1 U26.4 U27.61 | length 690.9
  Bottom Layer w8.7: U27.61@1428.27,590.55 1428.27,553.11 1438.86,542.52 1438.86,345.3 1453.98,330.18 1552.38,330.18 1630.27,408.07 R185.1@1679.65,408.07 1705.73,408.07 1711.53,402.27 U26.4@1751.97,402.27 1793.83,402.27 1802.35,410.79 R184.1@1802.35,444.06
EEPROM_A2: R161.1 R162.2 U11.3 | length 95
  Top Layer w10.8: U11.3@590.19,2568.79 R162.2@645.19,2568.79 R161.1@645.19,2528.79
EEPROM_WPn: R157.1 R158.2 U11.7 | length 181.4
  Top Layer w10.8: U11.7@376.18,2518.23 420.37,2518.23 435.36,2503.23 R157.1@435.36,2424.24 R158.2@435.36,2387.24
FTDI_3V3: C138.1 C149.2 C150.1 C151.2 C152.1 C153.1 L2.1 L3.1 L7.2 R167.2 R168.2 R184.2 R237.1 U26.8 U27.20 U27.31 U27.42 U27.50 U27.56 | length 2540.4
  Top Layer w18: v2(1610.75,329.31) 1637.2,302.86 1860.46,302.86 1919.49,361.88 1919.49,519.3 1907.24,531.55 1907.24,794.49 1876.36,825.37 v2(1833.68,825.37)
  Bottom Layer w10: U27.20@1428.27,1027.56 1428.27,1076.05 ; 1644.79,532.54 U27.50@1644.79,555.31 ; U27.31@1644.8,1027.56 1644.8,1069.89 ; U27.42@1735.35,779.53 C151.2@1815.35,779.53
  Bottom Layer w12: 1180.4,1005.35 L3.1@1180.46,979.36 L3.1@1180.46,979.36 ; 1428.27,1076.05 1463.28,1111.06 1463.28,1159.74 1456.25,1166.77 v2(1439.91,1166.77) ; v2(1610.75,329.31) v2@1610.92,329.48 ; R167.2@1634.28,329.48 R167.2@1634.45,329.65 ; 1644.8,532.53 1651.79,525.54 C150.1@1651.79,512.55
  Bottom Layer w13: C138.1@2046.31,325.57 C138.1@2046.38,325.5
  Bottom Layer w15: v2(1099.02,819.89) 1121.74,797.17 L2.1@1121.74,773.8 ; 1180.4,1005.35 1180.4,1051.62 1211.55,1082.77 1211.55,1162.63 1235.27,1186.35 1314.72,1186.35 1328.89,1172.18 1328.89,1135.76 v2(1329.03,1135.62) ; R237.1@1328.96,1104.84 v2@1328.96,1136.91 ; 1644.8,1069.89 1662.22,1087.31 C152.1@1662.22,1116.32 1700.33,1116.32 1714.35,1130.34 1714.35,1159.58 1751.27,1159.58 1867.67,1043.17 1945.81,1043.17 1989.99,999 1989.99,847.64 1968.08,825.73 1833.21,825.73 1815.35,807.87 C151.2@1815.35,779.53
  Bottom Layer w18: v2@1610.92,329.48 R167.2@1634.28,329.48
  Bottom Layer w20: C138.1@2046.31,325.5 C138.1@2046.31,325.57
  other v2: 1674.82,256.18 2046.61,352.58 1180.4,1020.35
FTDI_12C_SDA_IN: R100.1 U27.27 | length 84.5
  Top Layer w10.8: v2(1566.04,963.74) 1566.12,963.65 1566.12,943.25 R100.1@1566.21,943.16
  Bottom Layer w8.7: v2(1566.04,963.74) U27.27@1566.05,1027.55
FTDI_12C_SDA_OUT: R102.1 U27.28 | length 137.5
  Top Layer w10.8: R102.1@1640.77,932.52 1640.89,932.64 v2(1640.89,961.95)
  Bottom Layer w8.7: U27.28@1585.75,1027.56 1585.75,983.66 1607.46,961.95 v2(1640.89,961.95)
FTDI_DCA_LP_RS232_RX: U12.2 U18.3 | length 546.2
  Top Layer w10.8: U12.2@792.92,2403.24 792.92,2455.11 v2(806.27,2468.46) ; v2(1169.43,2482.21) 1172.09,2484.87 U18.3@1172.09,2541.56
  L6_SIG2 w6: v2(806.27,2468.46) 844.49,2506.68 1051.13,2506.68 1071.45,2527 1140,2527 1169.43,2497.57 v2(1169.43,2482.21)
FTDI_DCA_LP_RS232_TX: U12.14 U18.15 | length 618.7
  Top Layer w10.8: v2@809.06,2558.07 v2(809.22,2558.24) 818.51,2567.53 U12.14@818.51,2635.52 ; v2(1128.94,2710.63) 1146.5,2728.19 U18.15@1146.5,2773.84
  L6_SIG2 w6: v2(809.22,2558.24) 844.84,2522.63 1032.59,2522.63 1129.88,2619.92 1129.88,2709.69 v2(1128.94,2710.63)
FTDI_HOST_INTR_1: R216.2 R217.2 U28.18 | length 2529
  L6_SIG2 w6: v2(1779.62,977.54) 1779.62,962.16 1774.59,957.13 1733.97,957.13 1726.17,949.33 1726.17,938.93 1733.97,931.13 1771.82,931.13 1779.62,923.33 1779.62,920.33 1779.62,907.41 1790.17,896.86 2083.1,896.86 2174.52,988.29 2316.92,988.29 2665.76,1337.12 2758.9,1337.12 2796.82,1375.04 2936.88,1375.04 2942.88,1369.04 2942.88,1311.04 2948.88,1305.04 2960.88,1305.04 2966.88,1311.04 2966.88,1369.04 2972.88,1375.04 2984.88,1375.04 2990.88,1369.04 2990.88,1311.04 2996.88,1305.04 3008.88,1305.04 3014.88,1311.04 3014.88,1369.04 3020.88,1375.04 3032.88,1375.04 3038.88,1369.04 3038.88,1334.62 3044.88,1328.62 3056.88,1328.62 3062.88,1334.62 3062.88,1369.04 3068.88,1375.04 3080.88,1375.04 3086.88,1369.04 3086.88,1346.04 3092.88,1340.04 3230.74,1340.04 3238.28,1332.5 3238.28,1324.96 3231.81,1318.49 3175.46,1318.49 v2(3175.13,1318.81)
  Bottom Layer w8.7: R216.2@1738.12,1062.08 R217.2@1738.12,1027.08 1738.12,994.22 1754.8,977.54 v2(1779.62,977.54) ; v2(3175.13,1318.81) 3198.59,1342.28 U28.18@3198.59,1465.05
FTDI_I2C_SCL: R96.1 U27.26 | length 105.5
  Top Layer w10.8: R96.1@1500.42,956.46 1500.59,956.63 1526.87,956.63 v2(1527.04,956.79)
  Bottom Layer w8.7: v2(1527.04,956.79) 1546.38,976.13 U27.26@1546.38,1027.56
FTDI_MISO: R189.1 U27.18 | length 267.3
  Bottom Layer w8.7: U27.18@1388.9,1027.56 1388.87,1223.34 1422.21,1256.68 R189.1@1446.65,1256.68
FTDI_MOSI: R187.1 U27.17 | length 214.8
  Bottom Layer w8.7: R187.1@1350.56,1234.64 1350.56,1190.73 1369.21,1172.07 U27.17@1369.21,1027.56
FTDI_RS232_RX: R120.2 U12.1 | length 2717.4
  Top Layer w10.8: v2(752.42,2333.27) 767.33,2348.18 U12.1@767.33,2403.24
  L3_SIG1 w6: v2(752.42,2333.27) 729.63,2310.48 729.63,2233.12 784.76,2177.98 784.76,2006.36 751.02,1972.62 751.02,1882.98 787.54,1846.46 886.58,1846.46 922.86,1810.19 922.86,1711.87 873.17,1662.18 873.17,1532.9 896.38,1509.68 896.38,1263.29 1116.62,1043.05 1116.62,892.52 1366.21,642.93 v2(1387.3,642.93)
  L6_SIG2 w6: v2(1387.3,642.93) 1422.72,607.5 1664.54,607.5 1704.04,647 1843.36,647 v2(1857.78,661.42)
  Bottom Layer w6: R120.2@1835.71,661.42 v2(1857.78,661.42)
FTDI_RS232_TX: R121.2 U12.13 | length 2651
  Top Layer w10.8: U12.13@844.1,2635.52 844.1,2582.03 847.61,2578.52 v2(847.61,2551.43)
  L3_SIG1 w6: v2(847.61,2551.43) 847.61,2549.33 828.58,2530.29 828.58,2397.64 954.33,2271.88 954.33,1636.68 925.03,1607.38 925.03,1547.97 1006.32,1466.68 1062.26,1466.68 1160.59,1368.34 1160.59,956.3 1336.48,780.42 1447.58,780.42 1556.59,671.41 v2(1556.59,438.17)
  Bottom Layer w8.7: v2(1556.59,438.17) 1556.9,438.49 1556.9,458.22 R121.2@1557.21,458.53
FTDI_SOP0: R13.1 R43.2 R235.1 R249.2 | length 1491.4
  Top Layer w10.8: v2(301.11,604.49) 300.4,605.2 300.4,643.78 R13.1@299.69,644.49 R43.2@349.69,644.49 R235.1@349.69,674.49
  L6_SIG2 w6: v2(301.11,604.49) 477.6,428 1035,428 1108.44,354.56 v2(1513.63,354.56)
  Bottom Layer w8.7: R249.2@1468.31,377.48 1490.71,377.48 v2(1513.63,354.56)
FTDI_SOP1: R16.1 R67.2 R244.1 R248.2 | length 897
  Top Layer w10.8: R244.1@854.54,337.37 R67.2@854.54,377.37 854.54,393.12 R16.1@834.1,413.57 838.34,417.81 892.85,417.81 924.62,449.58 1029.74,449.58 1092.18,512.02 1322.26,512.02 1449.76,384.52 v2(1519.2,384.52)
  Bottom Layer w8.7: v2(1519.2,384.52) R248.2@1519.18,418.15
FTDI_SPI_CLK: R186.2 U28.11 | length 2539.4
  L6_SIG2 w6: v2(1292.87,1155.62) 1380.11,1155.62 1396.43,1139.31 1975.52,1139.31 2050.5,1064.32 2344.58,1064.32 2632.27,1352.01 2750.32,1352.01 2864.83,1466.51 2990.49,1466.51 3004.67,1480.69 3250.97,1480.69 3283,1512.72 3283,1560.31 v2(3222.89,1620.42)
  Bottom Layer w8.7: R186.2@1273.96,1104.79 1273.96,1136.71 v2(1292.87,1155.62) ; v2(3222.89,1620.42) 3272.64,1620.42 3300.96,1648.73 U28.11@3300.96,1693.39
FTDI_SPI_CS: R99.1 R209.2 U28.13 | length 2462.6
  L6_SIG2 w6: v2(1571.23,1251.23) 1571.23,1323.26 1601.97,1354 1633.13,1354 1640.93,1361.8 1640.93,1386.16 1648.73,1393.96 1659.13,1393.96 1666.93,1386.16 1666.93,1358.98 1674.73,1351.18 1685.13,1351.18 1692.93,1358.98 1692.93,1386.16 1700.73,1393.96 1711.13,1393.96 1718.93,1386.16 1718.93,1358.98 1726.73,1351.18 1737.13,1351.18 1744.93,1358.98 1744.93,1386.16 1752.73,1393.96 1763.13,1393.96 1770.93,1386.16 1770.93,1361.8 1778.73,1354 1985.04,1354 2029.41,1309.64 2187.88,1309.64 2291.65,1413.4 2364.99,1413.4 2453.48,1501.9 2779.26,1501.9 2867.86,1590.51 2933.76,1590.51 3011.05,1667.8 3253.57,1667.8 3311.23,1610.14 v2(3311.23,1581.08)
  Bottom Layer w8.7: R209.2@1510.53,1211.99 R99.1@1570.53,1211.99 1570.53,1250.53 v2(1571.23,1251.23) ; v2@3310.85,1581.01 3310.85,1560.97 3326.55,1545.27 U28.13@3326.55,1465.05
FTDI_SPI_MISO: R189.2 U28.15 | length 2415.5
  L6_SIG2 w6: v2(1512.56,1256.51) 1512.56,1238.36 1520.63,1230.28 1730.51,1230.28 1772.01,1230.28 1779.81,1238.08 1779.81,1272.33 1787.61,1280.13 1798.01,1280.13 1805.81,1272.33 1805.81,1236 1813.61,1228.2 1824.01,1228.2 1831.81,1236 1831.81,1272.33 1839.61,1280.13 1850.01,1280.13 1857.81,1272.33 1857.81,1236 1865.61,1228.2 1876.01,1228.2 1883.81,1236 1883.81,1272.33 1891.61,1280.13 1902.01,1280.13 1909.81,1272.33 1909.81,1236 1917.61,1228.2 1928.01,1228.2 1935.81,1236 1935.81,1272.33 1943.61,1280.13 1954.01,1280.13 1961.81,1272.33 1961.81,1238.08 1969.61,1230.28 1998.61,1230.28 2196.85,1230.28 2262.69,1296.12 2373.5,1296.12 2478.56,1401.18 2716.75,1401.18 2890.9,1575.33 2939.07,1575.33 2970.74,1607 3137.75,1607 3198.57,1546.18 3241.9,1546.18 v2(3253.82,1558.11)
  Bottom Layer w8.7: R189.2@1487,1256.68 1487.38,1257.06 1512.01,1257.06 v2(1512.56,1256.51) ; v2(3253.82,1558.11) 3254.67,1558.11 3275.37,1537.42 U28.15@3275.37,1465.05
FTDI_SPI_MOSI: R187.2 U28.17 | length 2469.1
  L6_SIG2 w6: v2(1296.79,1262.78) 1358.57,1201 2210,1201 2279.16,1270.16 2509.85,1270.16 2607.49,1367.8 2741.3,1367.8 2852.02,1478.51 2985.52,1478.51 3018.05,1511.04 3028.85,1521.84 3028.85,1567.49 3036.65,1575.29 3047.05,1575.29 3054.85,1567.49 3054.85,1521.15 3062.65,1513.35 3073.05,1513.35 3080.85,1521.15 3080.85,1567.49 3088.65,1575.29 3099.05,1575.29 3106.85,1567.49 3106.85,1521.15 3114.65,1513.35 3125.05,1513.35 3132.85,1521.15 3132.85,1542.93 3140.65,1550.73 3151.05,1550.73 3158.85,1542.93 3158.85,1523.09 3166.65,1515.29 3179.98,1515.29 v2(3247.1,1515.29)
  Bottom Layer w8.7: v2(1296.79,1262.78) 1296.79,1260.26 1303.31,1253.73 R187.2@1303.31,1234.64 ; U28.17@3224.18,1465.05 3224.18,1505.85 3233.62,1515.29 v2(3247.1,1515.29)
FTDI_SPICLK: R186.1 U27.16 | length 149.6
  Bottom Layer w8.7: R186.1@1273.96,1057.54 1273.96,1017.09 1251.85,994.98 1251.85,970.1 1254.72,967.23 1254.72,965.61 1263.63,956.7 U27.16@1298.34,956.7
FTDI_SPICS: R209.1 U27.19 | length 219.5
  Bottom Layer w8.7: U27.19@1408.58,1027.56 1408.58,1178.43 1442.14,1211.99 R209.1@1463.28,1211.99
FTDI_SUSPEND_N: R251.2 R252.1 | length 55
  Bottom Layer w8.7: R251.2@1854.41,897.64 R252.1@1909.39,897.64
FTDI_UART_RX: R118.1 U27.38 | length 151
  Top Layer w10.8: v2(1638.33,836.75) 1638.33,849.3 1645.2,856.17 R118.1@1645.2,868.68
  Bottom Layer w8.7: v2(1638.33,836.75) 1638.33,853.44 1643.79,858.91 1702.99,858.91 1703.03,858.87 1734.76,858.87 U27.38@1735.35,858.27
FTDI_UART_TX: R119.1 U27.39 | length 72.2
  Top Layer w10.8: v2(1683.25,837.46) 1684.19,838.41 1701.15,838.41 R119.1@1702.09,839.35
  Bottom Layer w8.7: v2(1683.25,837.46) 1684.37,838.58 U27.39@1735.35,838.58
FTDI_UARTA_RX: R118.2 U16.4 | length 1352.4
  Top Layer w10.8: v2(1201.74,1817.64) 1214.65,1804.74 U16.4@1214.65,1762.65 ; R118.2@1604.84,868.68 1604.84,888.24 1618.65,902.05 v2(1619.45,902.05)
  L3_SIG1 w6: v2(1201.74,1817.64) 1131.24,1747.14 1131.24,1593.54 1238.62,1486.15 1238.62,1103.31 1439.89,902.05 v2(1619.45,902.05)
FTDI_UARTA_TX: R119.2 U16.2 | length 1274.9
  Top Layer w6: U16.2@1175.28,1753.8 U16.2@1175.28,1762.65
  Top Layer w10.8: v2(1171.49,1680.7) 1171.49,1702.37 1175.28,1706.15 U16.2@1175.28,1753.8 ; v2(1674.48,938.7) 1674.48,936.91 1667.24,929.67 1667.24,886.03 1673.57,879.7 R119.2@1702.09,879.7
  L3_SIG1 w6: v2(1171.49,1680.7) 1303.11,1549.09 1303.11,1371.67 1369.21,1305.56 1369.21,991.43 1421.94,938.7 v2(1674.48,938.7)
FTDI_USBD_N: J10.2 U27.7 U29.1 | length 3195.8
  Top Layer w7.5: U29.1@3794.05,1645.56 3796.08,1647.59 3804.75,1647.59 3806.51,1649.35 3843.94,1649.35 3849.7,1643.58 v2(3852.54,1643.58) 3855.39,1643.58 3861.64,1649.83 3873.11,1649.83 3876.03,1646.91 3926.98,1646.91 J10.2@3931.1,1642.79
  Bottom Layer w6: U27.7@1298.34,779.53 1329.44,779.53 1333.66,783.75 1535.25,783.75 1694.87,624.13 1912.28,624.13 2215.15,927 2768.68,927 2924.99,1083.31 3148.4,1083.31 3594,1528.91 3675.14,1528.91 3795.8,1649.58 3843.3,1649.58 3849.3,1643.58 v2(3852.54,1643.58)
FTDI_USBD_P: J10.3 U27.8 U29.2 | length 3196
  Top Layer w7.5: U29.2@3795.04,1665.25 3797.07,1663.22 3804.75,1663.22 3807.12,1660.85 3843.02,1660.85 3849.76,1667.59 v2(3852.55,1667.59) 3855.39,1667.59 3861.64,1661.33 3873.11,1661.33 3876.03,1664.25 3926.98,1664.25 J10.3@3931.1,1668.38
  Bottom Layer w6: U27.8@1298.34,799.21 1329.44,799.21 1333.91,794.75 1539.81,794.75 1699.43,635.13 1907.72,635.13 2210.6,938 2764.13,938 2920.43,1094.31 3143.84,1094.31 3589.45,1539.91 3670.58,1539.91 3791.25,1660.58 3843.29,1660.58 3850.3,1667.59 v2(3852.55,1667.59)
FTDI_USBID: J10.4 U29.4 | length 180.1
  Top Layer w10.8: U29.4@3771.42,1684.93 3771.42,1711.55 3786.79,1726.92 3818.79,1726.92 3851.74,1693.97 J10.4@3904.92,1693.97
FTDI_VBUS: C157.2 J10.1 L8.1 R259.2
FTDI_VCORE: C139.1 C140.1 C143.1 C144.1 U27.12 U27.37 U27.49 U27.64 | length 1533.3
  Top Layer w20: v2(1411.45,848.38) 1411.45,758.58 1467.76,702.26 1648.78,702.26 1705.61,645.43 v2(1705.61,600.58)
  Bottom Layer w9: 1660.07,877.96 U27.37@1735.35,877.96
  Bottom Layer w10: U27.12@1298.34,877.96 1381.79,878.03 ; 1664.49,547.15 U27.49@1664.49,590.55
  Bottom Layer w12: C140.1@1230.55,899.12 1236.37,893.31 1236.37,885.21 1243.53,878.05 U27.12@1298.34,877.96 ; C139.1@1369.13,510.74 1369.13,619.97 1363.09,626.01 1363.09,668.94 1381.52,687.37 1381.52,718.77 1400.09,737.34 v2(1432.69,737.34) ; 1381.79,878.03 v2(1411.45,848.38) 1494.37,848.38 1523.95,877.96 1660.07,877.96 ; 1664.49,547.15 1673.28,538.36 1687.62,538.36 1700.39,525.59 1728.92,525.59 1744.15,540.83 C144.1@1748.09,540.83 1748.09,589.1 C143.1@1747.93,589.26 1716.94,589.26 v2(1705.61,600.58)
